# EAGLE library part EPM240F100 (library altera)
EPM240F100 Auto generated by make-symbol-device-package-bsdl.ulp Rev. 36 Source: EPM240F100.BSD
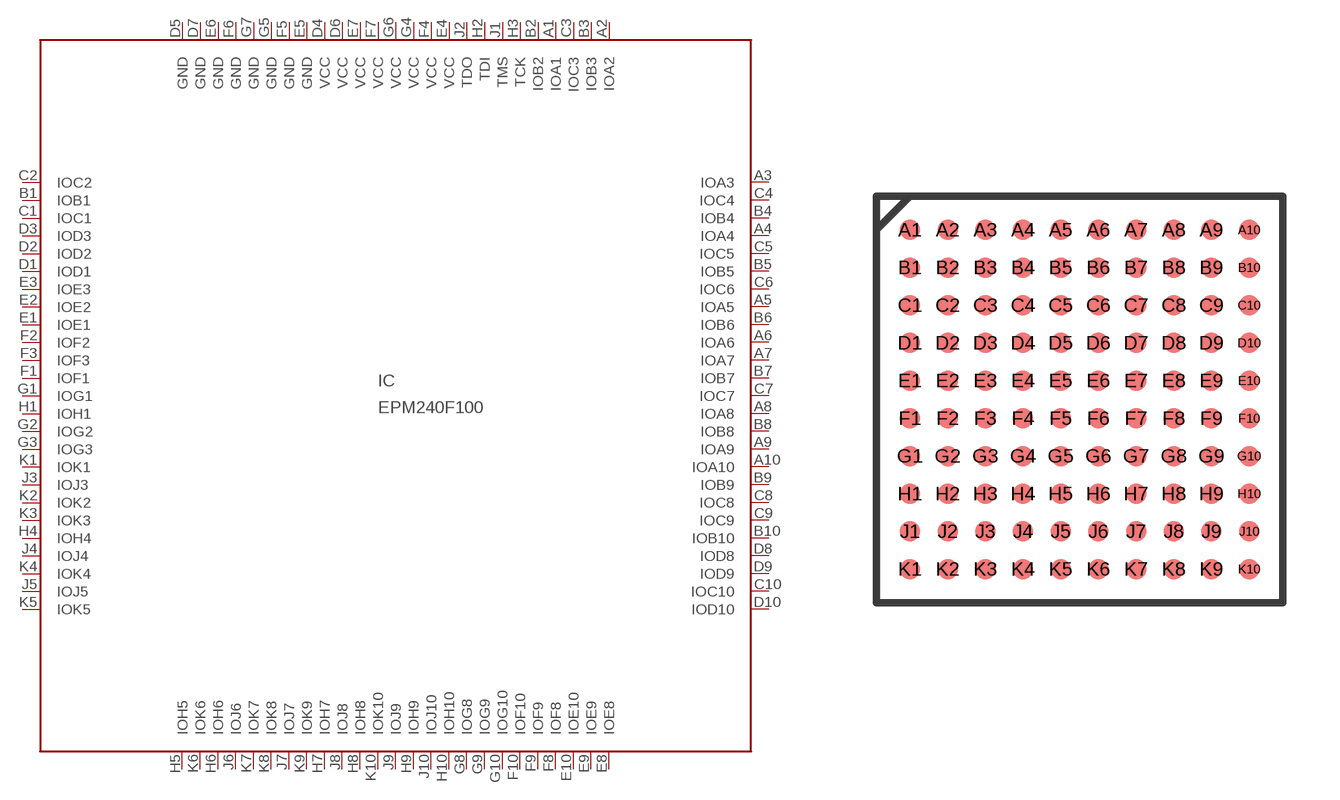
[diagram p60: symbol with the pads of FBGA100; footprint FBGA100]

Designator prefix IC

## EPM240F100 (MPN: SA800-B293; OC_FARNELL: 1635094; OC_NEWARK: 74R0178)  [FBGA100]
A1  IOA1
A2  IOA2
A3  IOA3
A4  IOA4
A5  IOA5
A6  IOA6
A7  IOA7
A8  IOA8
A9  IOA9
A10  IOA10
B1  IOB1
B2  IOB2
B3  IOB3
B4  IOB4
B5  IOB5
B6  IOB6
B7  IOB7
B8  IOB8
B9  IOB9
B10  IOB10
C1  IOC1
C2  IOC2
C3  IOC3
C4  IOC4
C5  IOC5
C6  IOC6
C7  IOC7
C8  IOC8
C9  IOC9
C10  IOC10
D1  IOD1
D2  IOD2
D3  IOD3
D4  VCC  pwr
D5  GND  pwr
D6  VCC  pwr
D7  GND  pwr
D8  IOD8
D9  IOD9
D10  IOD10
E1  IOE1
E2  IOE2
E3  IOE3
E4  VCC  pwr
E5  GND  pwr
E6  GND  pwr
E7  VCC  pwr
E8  IOE8
E9  IOE9
E10  IOE10
F1  IOF1
F2  IOF2
F3  IOF3
F4  VCC  pwr
F5  GND  pwr
F6  GND  pwr
F7  VCC  pwr
F8  IOF8
F9  IOF9
F10  IOF10
G1  IOG1
G2  IOG2
G3  IOG3
G4  VCC  pwr
G5  GND  pwr
G6  VCC  pwr
G7  GND  pwr
G8  IOG8
G9  IOG9
G10  IOG10
H1  IOH1
H2  TDI  in
H3  TCK  in
H4  IOH4
H5  IOH5
H6  IOH6
H7  IOH7
H8  IOH8
H9  IOH9
H10  IOH10
J1  TMS  in
J2  TDO  out
J3  IOJ3
J4  IOJ4
J5  IOJ5
J6  IOJ6
J7  IOJ7
J8  IOJ8
J9  IOJ9
J10  IOJ10
K1  IOK1
K2  IOK2
K3  IOK3
K4  IOK4
K5  IOK5
K6  IOK6
K7  IOK7
K8  IOK8
K9  IOK9
K10  IOK10

## Footprint FBGA100 (pad centres in mm)
EPM240F100 edit this description Auto generated by make-symbol-device-package-bsdl.ulp Rev. 36 Source: EPM240F100.BSD
smd 0.55 x 0.55: A1 -4.5,4.5; A2 -3.5,4.5; A3 -2.5,4.5; A4 -1.5,4.5; A5 -0.5,4.5; A6 0.5,4.5; A7 1.5,4.5; A8 2.5,4.5; A9 3.5,4.5; A10 4.5,4.5; B1 -4.5,3.5; B2 -3.5,3.5; B3 -2.5,3.5; B4 -1.5,3.5; B5 -0.5,3.5; B6 0.5,3.5; B7 1.5,3.5; B8 2.5,3.5; B9 3.5,3.5; B10 4.5,3.5; C1 -4.5,2.5; C2 -3.5,2.5; C3 -2.5,2.5; C4 -1.5,2.5; C5 -0.5,2.5; C6 0.5,2.5; C7 1.5,2.5; C8 2.5,2.5; C9 3.5,2.5; C10 4.5,2.5; D1 -4.5,1.5; D2 -3.5,1.5; D3 -2.5,1.5; D4 -1.5,1.5; D5 -0.5,1.5; D6 0.5,1.5; D7 1.5,1.5; D8 2.5,1.5; D9 3.5,1.5; D10 4.5,1.5; E1 -4.5,0.5; E2 -3.5,0.5; E3 -2.5,0.5; E4 -1.5,0.5; E5 -0.5,0.5; E6 0.5,0.5; E7 1.5,0.5; E8 2.5,0.5; E9 3.5,0.5; E10 4.5,0.5; F1 -4.5,-0.5; F2 -3.5,-0.5; F3 -2.5,-0.5; F4 -1.5,-0.5; F5 -0.5,-0.5; F6 0.5,-0.5; F7 1.5,-0.5; F8 2.5,-0.5; F9 3.5,-0.5; F10 4.5,-0.5; G1 -4.5,-1.5; G2 -3.5,-1.5; G3 -2.5,-1.5; G4 -1.5,-1.5; G5 -0.5,-1.5; G6 0.5,-1.5; G7 1.5,-1.5; G8 2.5,-1.5; G9 3.5,-1.5; G10 4.5,-1.5; H1 -4.5,-2.5; H2 -3.5,-2.5; H3 -2.5,-2.5; H4 -1.5,-2.5; H5 -0.5,-2.5; H6 0.5,-2.5; H7 1.5,-2.5; H8 2.5,-2.5; H9 3.5,-2.5; H10 4.5,-2.5; J1 -4.5,-3.5; J2 -3.5,-3.5; J3 -2.5,-3.5; J4 -1.5,-3.5; J5 -0.5,-3.5; J6 0.5,-3.5; J7 1.5,-3.5; J8 2.5,-3.5; J9 3.5,-3.5; J10 4.5,-3.5; K1 -4.5,-4.5; K2 -3.5,-4.5; K3 -2.5,-4.5; K4 -1.5,-4.5; K5 -0.5,-4.5; K6 0.5,-4.5; K7 1.5,-4.5; K8 2.5,-4.5; K9 3.5,-4.5; K10 4.5,-4.5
